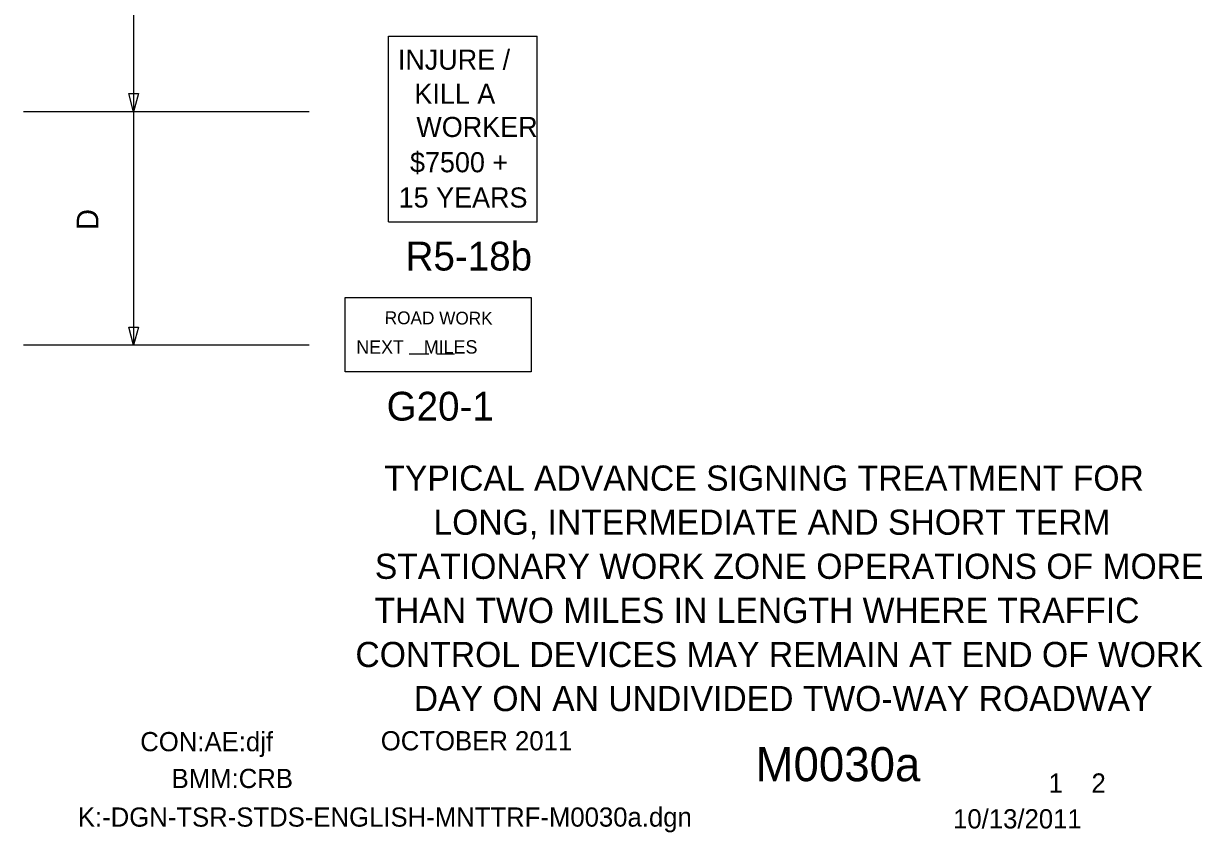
# Model space of a CAD drawing. Extents: x 16734 to 18468, y 5860 to 6911.
# Drawn here: x 17042.3 to 17422.6, y 5859.6 to 6120.8 of the extents above; entities that cross this region are included whole.
import ezdxf

# ---------------------------------------------------------------- set-up
doc = ezdxf.new("R2010")
doc.units = 0
for name, color, linetype in [('BORDER_SIGNAL_WO', 7, 'Continuous'), ('TRAFFIC_SIGNS_PR', 7, 'Continuous'), ('TYPICAL_EX', 7, 'Continuous'), ('TYPICAL_TEXT_DIMEN_PR', 7, 'Continuous')]:
    doc.layers.add(name, color=color, linetype=linetype)

msp = doc.modelspace()

# ---------------------------------------------------------------- linework, layer by layer
at = {"layer": 'TRAFFIC_SIGNS_PR'}
for p, q in [((17159.991, 6056.777), (17159.991, 6116.777)), ((17159.991, 6116.777), (17207.991, 6116.777)), ((17207.991, 6056.777), (17207.991, 6116.777)), ((17159.991, 6056.777), (17207.991, 6056.777))]:
    msp.add_line(p, q, dxfattribs=at)
at = {"layer": 'TYPICAL_TEXT_DIMEN_PR'}
for p, q in [((17077.798, 6167.853), (17077.798, 6017.069)), ((17077.808, 6092.304), (17076.237, 6098.166)), ((17076.237, 6098.166), (17077.808, 6098.166)), ((17077.808, 6098.166), (17079.379, 6098.166)), ((17079.379, 6098.166), (17077.808, 6092.304)), ((17042.296, 6092.412), (17134.43, 6092.412)), ((17077.808, 6016.912), (17076.237, 6022.774)), ((17076.237, 6022.774), (17077.808, 6022.774)), ((17077.808, 6022.774), (17079.379, 6022.774)), ((17079.379, 6022.774), (17077.808, 6016.912)), ((17042.296, 6017.02), (17134.43, 6017.02)), ((17166.709, 6014.142), (17173.058, 6014.142)), ((17175.65, 6014.142), (17181.352, 6014.142))]:
    msp.add_line(p, q, dxfattribs=at)
msp.add_lwpolyline([(17206.048, 6008.326), (17146.048, 6008.326), (17146.048, 6032.326), (17206.048, 6032.326)], close=True, dxfattribs=at)

# ---------------------------------------------------------------- texts
at = {"layer": 'BORDER_SIGNAL_WO'}
for s, height, p in [('CON:AE:djf', 6.2, (17079.93, 5885.858)), ('    OCTOBER 2011    ', 6.2, (17148.324, 5886.139)), ('    M0030a   ', 11, (17262.105, 5876.18)), ('BMM:CRB   ', 6.2, (17090.053, 5873.974)), (' 1    2 ', 6.2, (17370.692, 5872.498)), ('K:-DGN-TSR-STDS-ENGLISH-MNTTRF-M0030a.dgn        ', 6.2, (17059.797, 5861.511)), ('10/13/2011    ', 6.19999, (17342.171, 5860.93))]:
    msp.add_text(s, height=height, dxfattribs=at).set_placement(p)
at = {"layer": 'TRAFFIC_SIGNS_PR'}
for s, height, p in [('INJURE /', 6.5, (17163.039, 6105.892)), ('KILL A', 6.5, (17168.376, 6094.892)), ('WORKER', 6.5, (17169.011, 6084.171)), ('$7500 +', 6.5, (17166.962, 6072.778)), ('15 YEARS', 6.5, (17163.313, 6061.385)), ('R5-18b', 9.3, (17165.545, 6041.065)), ('G20-1', 9.3, (17159.428, 5992.603))]:
    msp.add_text(s, height=height, dxfattribs=at).set_placement(p)
at = {"layer": 'TYPICAL_EX'}
for s, p in [('TYPICAL ADVANCE SIGNING TREATMENT FOR ', (17158.687, 5969.987)), ('LONG, INTERMEDIATE AND SHORT TERM', (17174.529, 5955.751)), ('STATIONARY WORK ZONE OPERATIONS OF MORE', (17155.621, 5941.514)), ('THAN TWO MILES IN LENGTH WHERE TRAFFIC ', (17155.486, 5927.278)), ('CONTROL DEVICES MAY REMAIN AT END OF WORK', (17149.354, 5913.042)), (' DAY ON AN UNDIVIDED TWO-WAY ROADWAY', (17165.153, 5898.806))]:
    msp.add_text(s, height=8.12248, dxfattribs=at).set_placement(p)
at = {"layer": 'TYPICAL_TEXT_DIMEN_PR'}
for s, height, rotation, p in [('D', 7, 90, (17066.435, 6054.153)), ('ROAD WORK', 4.145, 359.69942, (17158.805, 6023.75)), ('NEXT    MILES', 4.31297, 0.09856, (17149.621, 6014.186))]:
    msp.add_text(s, height=height, rotation=rotation, dxfattribs=at).set_placement(p)

doc.saveas('drawing.dxf')
